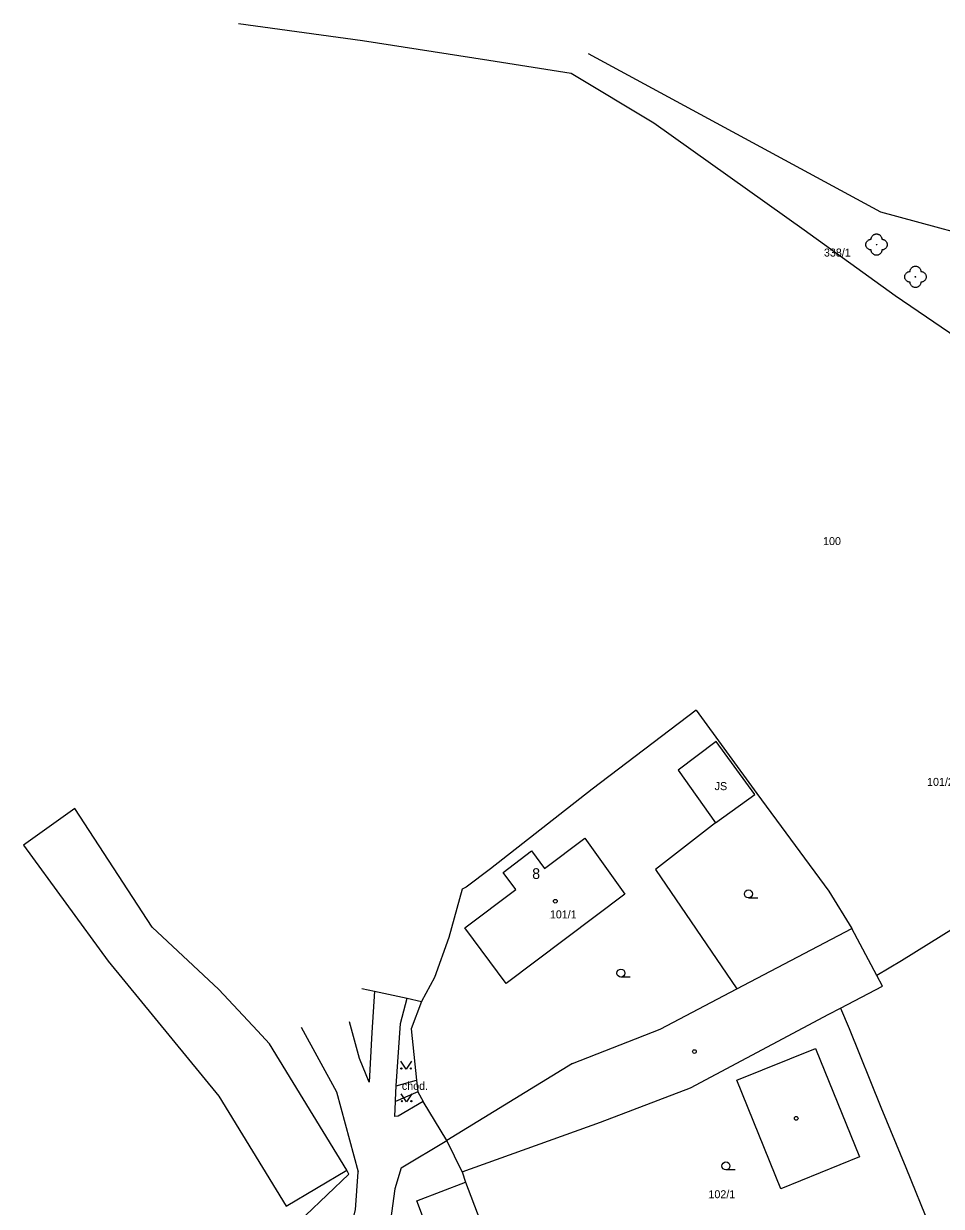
# Model space of a CAD drawing. Extents: x -836739 to -835945, y -1070775 to -1070126.
# Drawn here: x -836666.9 to -836580.9, y -1070275.3 to -1070164.5 of the extents above; entities that cross this region are included whole.
import ezdxf

# ---------------------------------------------------------------- set-up
doc = ezdxf.new("R2010")
doc.units = 0
for name, color, linetype in [('BodPole_mer', 7, 'Continuous'), ('Budovy_hranice', 7, 'Continuous'), ('Budovy_kody', 7, 'Continuous'), ('Doprava_hranice', 7, 'Continuous'), ('Doprava_kody', 7, 'Continuous'), ('OstPloch_hranice', 7, 'Continuous'), ('OstPloch_kody', 7, 'Continuous'), ('RuianAdr_popis', 7, 'Continuous'), ('RuianPar_popis', 7, 'Continuous'), ('Stavby_hr_stav', 7, 'Continuous'), ('Stavby_kody', 7, 'Continuous'), ('Stavby_linie', 7, 'Continuous'), ('Zelen_body', 7, 'Continuous'), ('Zelen_kody', 7, 'Continuous')]:
    doc.layers.add(name, color=color, linetype=linetype)

msp = doc.modelspace()

# ---------------------------------------------------------------- linework, layer by layer
at = {"layer": 'BodPole_mer'}
for p, q in [((-836586.56, -1070182.14), (-836586.56, -1070182.14)), ((-836586.96, -1070185.18), (-836586.96, -1070185.18)), ((-836583.31, -1070188.2), (-836583.31, -1070188.2)), ((-836585.2, -1070189.95), (-836585.2, -1070189.95)), ((-836603.88, -1070228.81), (-836603.88, -1070228.81)), ((-836601.99, -1070231.75), (-836601.99, -1070231.75)), ((-836605.55, -1070234.45), (-836605.55, -1070234.45)), ((-836613.63, -1070236.21), (-836613.63, -1070236.21)), ((-836598.36, -1070236.73), (-836598.36, -1070236.73)), ((-836598.18, -1070236.64), (-836598.18, -1070236.64)), ((-836602.06, -1070239.38), (-836602.06, -1070239.38)), ((-836614.32, -1070240.82), (-836614.32, -1070240.82)), ((-836619.31, -1070242.01), (-836619.31, -1070242.01)), ((-836623.15, -1070243.7), (-836623.15, -1070243.7)), ((-836621.98, -1070244.03), (-836621.98, -1070244.03)), ((-836618.1, -1070243.64), (-836618.1, -1070243.64)), ((-836607.7, -1070243.75), (-836607.7, -1070243.75)), ((-836625.43, -1070245.4), (-836625.43, -1070245.4)), ((-836620.77, -1070245.62), (-836620.77, -1070245.62)), ((-836610.55, -1070246.07), (-836610.55, -1070246.07)), ((-836591.42, -1070245.79), (-836591.42, -1070245.79)), ((-836625.57, -1070249.21), (-836625.57, -1070249.21)), ((-836589.27, -1070249.28), (-836589.27, -1070249.28)), ((-836627.07, -1070250.13), (-836627.07, -1070250.13)), ((-836584.63, -1070252.32), (-836584.63, -1070252.32)), ((-836628.42, -1070253.86), (-836628.42, -1070253.86)), ((-836621.7, -1070254.43), (-836621.7, -1070254.43)), ((-836586.94, -1070253.69), (-836586.94, -1070253.69)), ((-836600.07, -1070254.94), (-836600.07, -1070254.94)), ((-836586.41, -1070254.69), (-836586.41, -1070254.69)), ((-836629.62, -1070256.11), (-836629.62, -1070256.11)), ((-836590.34, -1070256.75), (-836590.34, -1070256.75)), ((-836591.44, -1070257.32), (-836591.44, -1070257.32)), ((-836631.6, -1070258.18), (-836631.6, -1070258.18)), ((-836630.59, -1070258.68), (-836630.59, -1070258.68)), ((-836607.26, -1070258.71), (-836607.26, -1070258.71)), ((-836589.54, -1070258.64), (-836589.54, -1070258.64)), ((-836592.67, -1070260.51), (-836592.67, -1070260.51)), ((-836615.47, -1070261.93), (-836615.47, -1070261.93)), ((-836634.53, -1070263.68), (-836634.53, -1070263.68)), ((-836632.01, -1070264.01), (-836632.01, -1070264.01)), ((-836630.1, -1070263.49), (-836630.1, -1070263.49)), ((-836604.42, -1070264.2), (-836604.42, -1070264.2)), ((-836600.05, -1070263.5), (-836600.05, -1070263.5)), ((-836632.08, -1070265.37), (-836632.08, -1070265.37)), ((-836632.08, -1070265.5), (-836632.08, -1070265.5)), ((-836629.96, -1070264.58), (-836629.96, -1070264.58)), ((-836629.48, -1070265.5), (-836629.48, -1070265.5)), ((-836586.56, -1070266.03), (-836586.56, -1070266.03)), ((-836632.14, -1070266.89), (-836632.14, -1070266.89)), ((-836631.82, -1070266.88), (-836631.82, -1070266.88)), ((-836612.83, -1070267.44), (-836612.83, -1070267.44)), ((-836627.26, -1070269.14), (-836627.26, -1070269.14)), ((-836588.55, -1070270.68), (-836588.55, -1070270.68)), ((-836636.64, -1070271.92), (-836636.64, -1070271.92)), ((-836635.58, -1070272.1), (-836635.58, -1070272.1)), ((-836631.53, -1070271.72), (-836631.53, -1070271.72)), ((-836625.81, -1070272.09), (-836625.81, -1070272.09)), ((-836584.21, -1070271.67), (-836584.21, -1070271.67)), ((-836636.43, -1070272.29), (-836636.43, -1070272.29)), ((-836625.49, -1070273.06), (-836625.49, -1070273.06)), ((-836632.14, -1070273.69), (-836632.14, -1070273.69)), ((-836595.94, -1070273.68), (-836595.94, -1070273.68)), ((-836630.08, -1070274.8), (-836630.08, -1070274.8))]:
    msp.add_line(p, q, dxfattribs=at)
at = {"layer": 'Budovy_hranice'}
for p, q in [((-836600.05, -1070263.5), (-836592.67, -1070260.51)), ((-836592.67, -1070260.51), (-836588.55, -1070270.68)), ((-836615.47, -1070261.93), (-836627.26, -1070269.14)), ((-836595.94, -1070273.68), (-836600.05, -1070263.5)), ((-836625.81, -1070272.09), (-836627.26, -1070269.14)), ((-836588.55, -1070270.68), (-836595.94, -1070273.68))]:
    msp.add_line(p, q, dxfattribs=at)
for points in [[(-836642.32, -1070275.31), (-836636.64, -1070271.92), (-836643.89, -1070260.1), (-836645.02, -1070258.88), (-836648.63, -1070254.99), (-836654.88, -1070249.15), (-836662.15, -1070238.02), (-836666.94, -1070241.48), (-836659.01, -1070252.35), (-836648.63, -1070265), (-836642.32, -1070275.31)], [(-836621.7, -1070254.43), (-836625.57, -1070249.21), (-836620.77, -1070245.62), (-836621.98, -1070244.03), (-836619.31, -1070242.01), (-836618.1, -1070243.64), (-836614.32, -1070240.82), (-836610.55, -1070246.07), (-836621.7, -1070254.43)], [(-836625.81, -1070272.09), (-836612.83, -1070267.44), (-836604.42, -1070264.2), (-836591.44, -1070257.32), (-836590.34, -1070256.75), (-836586.41, -1070254.69), (-836586.94, -1070253.69), (-836589.27, -1070249.28)], [(-836615.47, -1070261.93), (-836607.26, -1070258.71), (-836600.07, -1070254.94), (-836589.27, -1070249.28)], [(-836627.41, -1070281.86), (-836630.08, -1070274.8), (-836625.49, -1070273.06), (-836622.82, -1070280.13), (-836627.41, -1070281.86)]]:
    msp.add_lwpolyline(points, dxfattribs=at)
at = {"layer": 'Budovy_kody'}
for centre in [(-836617.08, -1070246.72), (-836604.04, -1070260.81), (-836594.49, -1070267.07)]:
    msp.add_circle(centre, 0.175, dxfattribs=at)
at = {"layer": 'Doprava_hranice'}
for p, q in [((-836632.01, -1070264.01), (-836630.1, -1070263.49)), ((-836629.96, -1070264.58), (-836632.08, -1070265.5)), ((-836631.53, -1070271.72), (-836627.26, -1070269.14))]:
    msp.add_line(p, q, dxfattribs=at)
for points in [[(-836634.03, -1070255.16), (-836634.28, -1070259.04), (-836634.53, -1070263.68), (-836635.45, -1070261.45), (-836636.38, -1070258.03)], [(-836629.48, -1070265.5), (-836631.82, -1070266.88), (-836632.14, -1070266.89), (-836632.08, -1070265.5), (-836632.08, -1070265.37), (-836632.01, -1070264.01), (-836631.6, -1070258.18), (-836630.97, -1070255.82)], [(-836640.93, -1070258.54), (-836637.6, -1070264.59), (-836635.58, -1070272.1)], [(-836639.59, -1070284.96), (-836637.77, -1070281.1), (-836636.66, -1070278.93), (-836635.83, -1070275.65), (-836635.58, -1070272.1)], [(-836631.53, -1070271.72), (-836632.14, -1070273.69), (-836632.77, -1070278.23), (-836632.91, -1070282.53), (-836632.11, -1070285.29), (-836630.35, -1070289), (-836629.24, -1070291.58), (-836627.52, -1070296.42), (-836624.89, -1070303.46), (-836621.3, -1070314.92), (-836620.43, -1070319.36), (-836619.2, -1070321.11), (-836614.79, -1070322.41)]]:
    msp.add_lwpolyline(points, dxfattribs=at)
at = {"layer": 'OstPloch_hranice'}
msp.add_lwpolyline([(-836564.73, -1070184.21), (-836574.34, -1070185.45), (-836586.56, -1070182.14), (-836613.97, -1070167.29)], dxfattribs=at)
at = {"layer": 'OstPloch_kody'}
for p, q in [((-836598.09, -1070246.42), (-836598.97, -1070246.42)), ((-836610.06, -1070253.84), (-836610.93, -1070253.84)), ((-836600.21, -1070271.91), (-836601.08, -1070271.91))]:
    msp.add_line(p, q, dxfattribs=at)
for centre in [(-836598.97, -1070246.04), (-836610.93, -1070253.46), (-836601.08, -1070271.53)]:
    msp.add_ellipse(centre, major_axis=(0.375, 0), ratio=0.999999, dxfattribs=at)
at = {"layer": 'RuianAdr_popis'}
msp.add_line((-836619.25, -1070244.63), (-836619.25, -1070244.63), dxfattribs=at)
at = {"layer": 'RuianPar_popis'}
for p, q in [((-836591.89, -1070186.3), (-836591.89, -1070186.3)), ((-836591.97, -1070213.34), (-836591.97, -1070213.34)), ((-836582.22, -1070235.91), (-836582.22, -1070235.91)), ((-836617.59, -1070248.33), (-836617.59, -1070248.33)), ((-836602.72, -1070274.56), (-836602.72, -1070274.56))]:
    msp.add_line(p, q, dxfattribs=at)
at = {"layer": 'Stavby_hr_stav'}
msp.add_lwpolyline([(-836605.55, -1070234.45), (-836602.06, -1070239.38), (-836598.36, -1070236.73), (-836601.99, -1070231.75), (-836605.55, -1070234.45)], dxfattribs=at)
at = {"layer": 'Stavby_linie'}
for p, q in [((-836602.06, -1070239.38), (-836607.7, -1070243.75)), ((-836607.7, -1070243.75), (-836600.07, -1070254.94)), ((-836627.26, -1070269.14), (-836629.48, -1070265.5)), ((-836625.81, -1070272.09), (-836625.49, -1070273.06))]:
    msp.add_line(p, q, dxfattribs=at)
for points in [[(-836646.79, -1070164.47), (-836635.17, -1070166.04), (-836623.33, -1070167.88), (-836615.58, -1070169.1), (-836607.83, -1070173.77), (-836593.75, -1070183.78), (-836585.2, -1070189.95), (-836577.96, -1070194.89), (-836571.5, -1070200.08), (-836562.11, -1070207.9), (-836555.43, -1070213.46), (-836552.63, -1070222.02), (-836550.05, -1070228.71)], [(-836603.88, -1070228.81), (-836613.63, -1070236.21), (-836623.15, -1070243.7), (-836625.43, -1070245.4)], [(-836603.88, -1070228.81), (-836598.18, -1070236.64), (-836591.42, -1070245.79), (-836589.27, -1070249.28)], [(-836625.43, -1070245.4), (-836625.83, -1070245.6), (-836627.07, -1070250.13), (-836628.42, -1070253.86), (-836629.62, -1070256.11), (-836630.59, -1070258.68), (-836630.1, -1070263.49), (-836629.96, -1070264.58), (-836629.48, -1070265.5)], [(-836577.07, -1070247.73), (-836578.34, -1070248.4), (-836584.63, -1070252.32), (-836586.94, -1070253.69)], [(-836635.23, -1070254.9), (-836634.03, -1070255.16), (-836630.97, -1070255.82), (-836629.62, -1070256.11)], [(-836590.34, -1070256.75), (-836589.54, -1070258.64), (-836586.56, -1070266.03), (-836584.21, -1070271.67), (-836581.93, -1070277.31), (-836580.96, -1070280.12)], [(-836641.58, -1070277.2), (-836640.52, -1070276.19), (-836636.43, -1070272.29), (-836636.64, -1070271.92)]]:
    msp.add_lwpolyline(points, dxfattribs=at)
at = {"layer": 'Zelen_body'}
for p, q in [((-836586.96, -1070185.18), (-836586.96, -1070185.18)), ((-836583.31, -1070188.2), (-836583.31, -1070188.2))]:
    msp.add_line(p, q, dxfattribs=at)
for points in [[(-836587.46, -1070185.68), (-836587.51, -1070185.68), (-836587.56, -1070185.67), (-836587.61, -1070185.66), (-836587.66, -1070185.64), (-836587.7, -1070185.62), (-836587.75, -1070185.59), (-836587.79, -1070185.55), (-836587.83, -1070185.51), (-836587.87, -1070185.47), (-836587.9, -1070185.42), (-836587.92, -1070185.38), (-836587.94, -1070185.33), (-836587.95, -1070185.28), (-836587.96, -1070185.23), (-836587.96, -1070185.18), (-836587.96, -1070185.13), (-836587.95, -1070185.08), (-836587.94, -1070185.03), (-836587.92, -1070184.98), (-836587.9, -1070184.94), (-836587.87, -1070184.89), (-836587.83, -1070184.85), (-836587.79, -1070184.81), (-836587.75, -1070184.77), (-836587.7, -1070184.74), (-836587.66, -1070184.72), (-836587.61, -1070184.7), (-836587.56, -1070184.69), (-836587.51, -1070184.68), (-836587.46, -1070184.68)], [(-836587.46, -1070184.68), (-836587.46, -1070184.63), (-836587.45, -1070184.58), (-836587.44, -1070184.53), (-836587.42, -1070184.48), (-836587.4, -1070184.44), (-836587.37, -1070184.39), (-836587.33, -1070184.35), (-836587.29, -1070184.31), (-836587.25, -1070184.27), (-836587.2, -1070184.24), (-836587.16, -1070184.22), (-836587.11, -1070184.2), (-836587.06, -1070184.19), (-836587.01, -1070184.18), (-836586.96, -1070184.18), (-836586.91, -1070184.18), (-836586.86, -1070184.19), (-836586.81, -1070184.2), (-836586.76, -1070184.22), (-836586.72, -1070184.24), (-836586.67, -1070184.27), (-836586.63, -1070184.31), (-836586.59, -1070184.35), (-836586.55, -1070184.39), (-836586.52, -1070184.44), (-836586.5, -1070184.48), (-836586.48, -1070184.53), (-836586.47, -1070184.58), (-836586.46, -1070184.63), (-836586.46, -1070184.68)], [(-836586.46, -1070184.68), (-836586.41, -1070184.68), (-836586.36, -1070184.69), (-836586.31, -1070184.7), (-836586.26, -1070184.72), (-836586.22, -1070184.74), (-836586.17, -1070184.77), (-836586.13, -1070184.81), (-836586.09, -1070184.85), (-836586.05, -1070184.89), (-836586.02, -1070184.94), (-836586, -1070184.98), (-836585.98, -1070185.03), (-836585.97, -1070185.08), (-836585.96, -1070185.13), (-836585.96, -1070185.18), (-836585.96, -1070185.23), (-836585.97, -1070185.28), (-836585.98, -1070185.33), (-836586, -1070185.38), (-836586.02, -1070185.42), (-836586.05, -1070185.47), (-836586.09, -1070185.51), (-836586.13, -1070185.55), (-836586.17, -1070185.59), (-836586.22, -1070185.62), (-836586.26, -1070185.64), (-836586.31, -1070185.66), (-836586.36, -1070185.67), (-836586.41, -1070185.68), (-836586.46, -1070185.68)], [(-836586.46, -1070185.68), (-836586.46, -1070185.73), (-836586.47, -1070185.78), (-836586.48, -1070185.83), (-836586.5, -1070185.88), (-836586.52, -1070185.92), (-836586.55, -1070185.97), (-836586.59, -1070186.01), (-836586.63, -1070186.05), (-836586.67, -1070186.09), (-836586.72, -1070186.12), (-836586.76, -1070186.14), (-836586.81, -1070186.16), (-836586.86, -1070186.17), (-836586.91, -1070186.18), (-836586.96, -1070186.18), (-836587.01, -1070186.18), (-836587.06, -1070186.17), (-836587.11, -1070186.16), (-836587.16, -1070186.14), (-836587.2, -1070186.12), (-836587.25, -1070186.09), (-836587.29, -1070186.05), (-836587.33, -1070186.01), (-836587.37, -1070185.97), (-836587.4, -1070185.92), (-836587.42, -1070185.88), (-836587.44, -1070185.83), (-836587.45, -1070185.78), (-836587.46, -1070185.73), (-836587.46, -1070185.68)], [(-836583.81, -1070188.7), (-836583.86, -1070188.7), (-836583.91, -1070188.69), (-836583.96, -1070188.68), (-836584.01, -1070188.66), (-836584.05, -1070188.64), (-836584.1, -1070188.61), (-836584.14, -1070188.57), (-836584.18, -1070188.53), (-836584.22, -1070188.49), (-836584.25, -1070188.44), (-836584.27, -1070188.4), (-836584.29, -1070188.35), (-836584.3, -1070188.3), (-836584.31, -1070188.25), (-836584.31, -1070188.2), (-836584.31, -1070188.15), (-836584.3, -1070188.1), (-836584.29, -1070188.05), (-836584.27, -1070188), (-836584.25, -1070187.96), (-836584.22, -1070187.91), (-836584.18, -1070187.87), (-836584.14, -1070187.83), (-836584.1, -1070187.79), (-836584.05, -1070187.76), (-836584.01, -1070187.74), (-836583.96, -1070187.72), (-836583.91, -1070187.71), (-836583.86, -1070187.7), (-836583.81, -1070187.7)], [(-836583.81, -1070187.7), (-836583.81, -1070187.65), (-836583.8, -1070187.6), (-836583.79, -1070187.55), (-836583.77, -1070187.5), (-836583.75, -1070187.46), (-836583.72, -1070187.41), (-836583.68, -1070187.37), (-836583.64, -1070187.33), (-836583.6, -1070187.29), (-836583.55, -1070187.26), (-836583.51, -1070187.24), (-836583.46, -1070187.22), (-836583.41, -1070187.21), (-836583.36, -1070187.2), (-836583.31, -1070187.2), (-836583.26, -1070187.2), (-836583.21, -1070187.21), (-836583.16, -1070187.22), (-836583.11, -1070187.24), (-836583.07, -1070187.26), (-836583.02, -1070187.29), (-836582.98, -1070187.33), (-836582.94, -1070187.37), (-836582.9, -1070187.41), (-836582.87, -1070187.46), (-836582.85, -1070187.5), (-836582.83, -1070187.55), (-836582.82, -1070187.6), (-836582.81, -1070187.65), (-836582.81, -1070187.7)], [(-836582.81, -1070187.7), (-836582.76, -1070187.7), (-836582.71, -1070187.71), (-836582.66, -1070187.72), (-836582.61, -1070187.74), (-836582.57, -1070187.76), (-836582.52, -1070187.79), (-836582.48, -1070187.83), (-836582.44, -1070187.87), (-836582.4, -1070187.91), (-836582.37, -1070187.96), (-836582.35, -1070188), (-836582.33, -1070188.05), (-836582.32, -1070188.1), (-836582.31, -1070188.15), (-836582.31, -1070188.2), (-836582.31, -1070188.25), (-836582.32, -1070188.3), (-836582.33, -1070188.35), (-836582.35, -1070188.4), (-836582.37, -1070188.44), (-836582.4, -1070188.49), (-836582.44, -1070188.53), (-836582.48, -1070188.57), (-836582.52, -1070188.61), (-836582.57, -1070188.64), (-836582.61, -1070188.66), (-836582.66, -1070188.68), (-836582.71, -1070188.69), (-836582.76, -1070188.7), (-836582.81, -1070188.7)], [(-836582.81, -1070188.7), (-836582.81, -1070188.75), (-836582.82, -1070188.8), (-836582.83, -1070188.85), (-836582.85, -1070188.9), (-836582.87, -1070188.94), (-836582.9, -1070188.99), (-836582.94, -1070189.03), (-836582.98, -1070189.07), (-836583.02, -1070189.11), (-836583.07, -1070189.14), (-836583.11, -1070189.16), (-836583.16, -1070189.18), (-836583.21, -1070189.19), (-836583.26, -1070189.2), (-836583.31, -1070189.2), (-836583.36, -1070189.2), (-836583.41, -1070189.19), (-836583.46, -1070189.18), (-836583.51, -1070189.16), (-836583.55, -1070189.14), (-836583.6, -1070189.11), (-836583.64, -1070189.07), (-836583.68, -1070189.03), (-836583.72, -1070188.99), (-836583.75, -1070188.94), (-836583.77, -1070188.9), (-836583.79, -1070188.85), (-836583.8, -1070188.8), (-836583.81, -1070188.75), (-836583.81, -1070188.7)]]:
    msp.add_lwpolyline(points, dxfattribs=at)
for centre in [(-836586.96, -1070185.18), (-836583.31, -1070188.2)]:
    msp.add_ellipse(centre, major_axis=(0.025, 0), ratio=0.999997, dxfattribs=at)
at = {"layer": 'Zelen_kody'}
for points in [[(-836630.57, -1070261.7), (-836631.07, -1070262.45), (-836631.57, -1070261.7)], [(-836630.53, -1070264.76), (-836631.03, -1070265.51), (-836631.53, -1070264.76)]]:
    msp.add_lwpolyline(points, dxfattribs=at)
for centre in [(-836631.52, -1070262.4), (-836630.62, -1070262.4), (-836631.48, -1070265.46), (-836630.58, -1070265.46)]:
    msp.add_circle(centre, 0.05, dxfattribs=at)

# ---------------------------------------------------------------- texts
at = {"layer": 'Doprava_kody'}
msp.add_text('chod.', height=0.75, dxfattribs=at).set_placement((-836631.47, -1070264.4))
at = {"layer": 'RuianAdr_popis'}
msp.add_text('8', height=1, dxfattribs=at).set_placement((-836619.25, -1070244.63))
at = {"layer": 'RuianPar_popis'}
for s, p in [('338/1', (-836591.89, -1070186.3)), ('100', (-836591.97, -1070213.34)), ('101/2', (-836582.22, -1070235.91)), ('101/1', (-836617.59, -1070248.33)), ('102/1', (-836602.72, -1070274.56))]:
    msp.add_text(s, height=0.75, dxfattribs=at).set_placement(p)
at = {"layer": 'Stavby_kody'}
msp.add_text('JS', height=0.75, dxfattribs=at).set_placement((-836602.14, -1070236.31))

doc.saveas('drawing.dxf')
